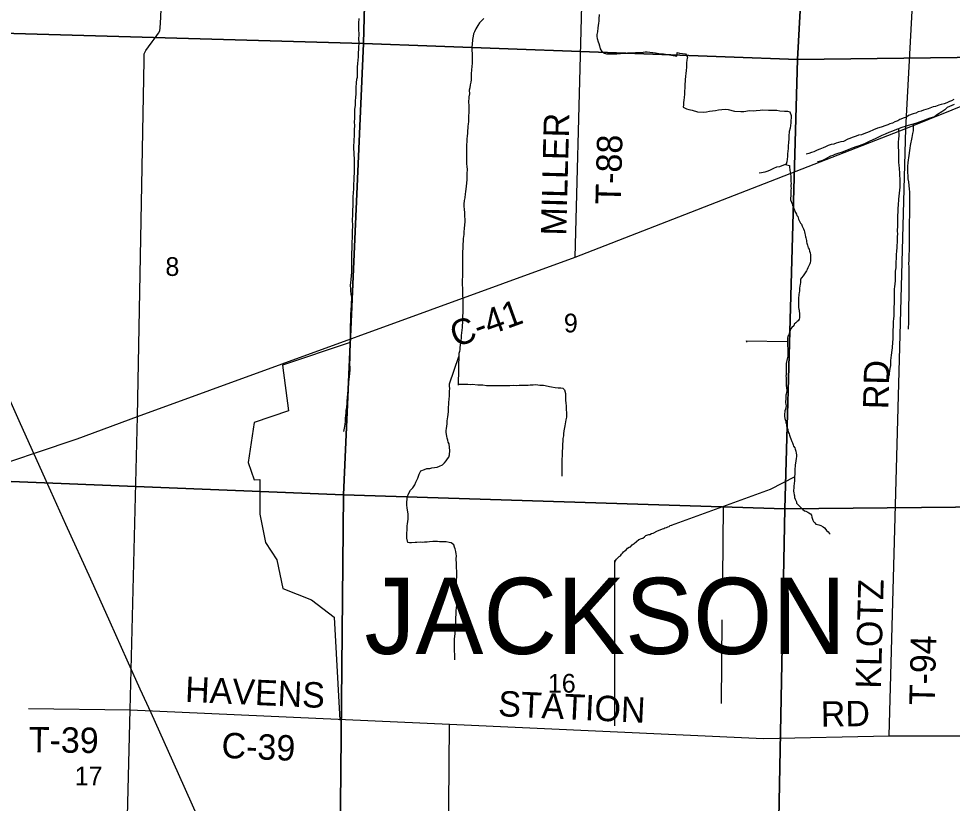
# Model space of a CAD drawing. Extents: x 1588073 to 2013523, y 1090242 to 1357120.
# Drawn here: x 1754621 to 1765643, y 1203633 to 1212899 of the extents above; entities that cross this region are included whole.
import ezdxf

# ---------------------------------------------------------------- set-up
doc = ezdxf.new("R2010")
doc.units = 0
for name, color, linetype in [('GM_X_County_Road', 7, 'Continuous'), ('GM_X_County_Road_Text', 7, 'Continuous'), ('GM_X_Minor_River', 7, 'Continuous'), ('GM_X_Rail_Line', 7, 'Continuous'), ('GM_X_Section', 7, 'Continuous'), ('GM_X_Section_Text', 7, 'Continuous'), ('GM_X_State_Route', 7, 'Continuous'), ('GM_X_Township_Road', 7, 'Continuous'), ('GM_X_Township_Road_Text', 7, 'Continuous'), ('GM_X_Township_Text', 7, 'Continuous')]:
    doc.layers.add(name, color=color, linetype=linetype)

msp = doc.modelspace()

# ---------------------------------------------------------------- linework, layer by layer
at = {"layer": 'GM_X_County_Road'}
for points in [[(1756023, 1208199), (1761191, 1210081), (1765096, 1211602), (1766978, 1212363), (1767188, 1212436), (1769131, 1212444)], [(1754830, 1207775), (1754830, 1207775), (1755311, 1207936), (1756023, 1208199)], [(1748340, 1207517), (1748351, 1207513), (1748389, 1207502), (1751177, 1207475), (1753182, 1207451), (1753244, 1207452), (1753738, 1207449), (1753898, 1207463), (1754315, 1207603), (1754830, 1207775)], [(1755938, 1204735), (1759706, 1204567), (1763414, 1204400), (1764898, 1204431), (1766414, 1204430)]]:
    msp.add_lwpolyline(points, dxfattribs=at)
at = {"layer": 'GM_X_Minor_River'}
for p, q in [((1758533, 1209074), (1757737, 1208807)), ((1763213, 1209094), (1763697, 1209086)), ((1763218, 1209079), (1763213, 1209094)), ((1757737, 1208807), (1757737, 1208807)), ((1757737, 1208807), (1757805, 1208266)), ((1757805, 1208266), (1757399, 1208130)), ((1757805, 1208266), (1757805, 1208266)), ((1757399, 1208130), (1757332, 1207657)), ((1757399, 1208130), (1757399, 1208130)), ((1757332, 1207657), (1757332, 1207657)), ((1757332, 1207657), (1757399, 1207454)), ((1757399, 1207454), (1757467, 1207455)), ((1757467, 1207455), (1757467, 1207049)), ((1763498, 1207344), (1763787, 1207493)), ((1762327, 1206918), (1763498, 1207344)), ((1763498, 1207344), (1763498, 1207344)), ((1762932, 1206284), (1762942, 1207142)), ((1757467, 1207049), (1757467, 1207049)), ((1757467, 1207049), (1757535, 1206711)), ((1757535, 1206711), (1757535, 1206711)), ((1757535, 1206711), (1757670, 1206508)), ((1757670, 1206508), (1757670, 1206508)), ((1757670, 1206508), (1757738, 1206170)), ((1761660, 1204549), (1761659, 1206499)), ((1757738, 1206170), (1757738, 1206170)), ((1757738, 1206170), (1758076, 1206035)), ((1758076, 1206035), (1758076, 1206035)), ((1758076, 1206035), (1758346, 1205832)), ((1758346, 1205832), (1758346, 1205832)), ((1758346, 1205832), (1758414, 1204616)), ((1762919, 1204812), (1762926, 1205801))]:
    msp.add_line(p, q, dxfattribs=at)
for points in [[(1758637, 1212901), (1758633, 1212844), (1758632, 1212782), (1758636, 1212706), (1758634, 1212664), (1758636, 1212612), (1758634, 1212558), (1758630, 1212474), (1758628, 1212447), (1758621, 1212369), (1758617, 1212327), (1758617, 1212259), (1758615, 1212203), (1758609, 1212179), (1758605, 1212147), (1758603, 1212084), (1758601, 1212060), (1758600, 1212018), (1758596, 1211962), (1758594, 1211936), (1758592, 1211900), (1758592, 1211878), (1758586, 1211826), (1758584, 1211778), (1758584, 1211713), (1758582, 1211689), (1758585, 1211625), (1758583, 1211599), (1758583, 1211535), (1758581, 1211513), (1758579, 1211473), (1758577, 1211449), (1758575, 1211393), (1758575, 1211359), (1758577, 1211323), (1758580, 1211218), (1758580, 1211178), (1758582, 1211104), (1758582, 1211076), (1758578, 1211032), (1758578, 1211006), (1758574, 1210928), (1758573, 1210895), (1758571, 1210837), (1758567, 1210799), (1758567, 1210773), (1758565, 1210749), (1758565, 1210683), (1758563, 1210643), (1758561, 1210595), (1758561, 1210561), (1758559, 1210539), (1758560, 1210438), (1758558, 1210404), (1758558, 1210338), (1758556, 1210310), (1758554, 1210264), (1758554, 1210242), (1758552, 1210170), (1758550, 1210148), (1758551, 1210101), (1758549, 1210035), (1758549, 1209903), (1758547, 1209871), (1758541, 1209809)], [(1760113, 1212901), (1760062, 1212848), (1760040, 1212820), (1760016, 1212780), (1760004, 1212744)], [(1761475, 1212949), (1761470, 1212896), (1761468, 1212868), (1761466, 1212846), (1761458, 1212792), (1761454, 1212744), (1761448, 1212712), (1761446, 1212690), (1761452, 1212664), (1761462, 1212626), (1761470, 1212604), (1761476, 1212580), (1761486, 1212544), (1761505, 1212512), (1761535, 1212490), (1761559, 1212484), (1761589, 1212482), (1761655, 1212482), (1761681, 1212484), (1761705, 1212486), (1761727, 1212486), (1761755, 1212490), (1761783, 1212492), (1761807, 1212494), (1761845, 1212494), (1761869, 1212497), (1761903, 1212499), (1761943, 1212501), (1761967, 1212501), (1761993, 1212505), (1762015, 1212507), (1762039, 1212507), (1762071, 1212503), (1762106, 1212501), (1762138, 1212497), (1762180, 1212489), (1762208, 1212485), (1762234, 1212482), (1762256, 1212478), (1762284, 1212474), (1762306, 1212470), (1762390, 1212457)], [(1760004, 1212744), (1759992, 1212720), (1759986, 1212694), (1759978, 1212654), (1759974, 1212592), (1759972, 1212565), (1759972, 1212519), (1759974, 1212491), (1759975, 1212435), (1759973, 1212405), (1759973, 1212365), (1759971, 1212343), (1759965, 1212287), (1759963, 1212257), (1759963, 1212178), (1759959, 1212150), (1759951, 1212116), (1759945, 1212082), (1759941, 1212054), (1759942, 1212010), (1759936, 1211976), (1759932, 1211904), (1759934, 1211882), (1759934, 1211785), (1759932, 1211757), (1759930, 1211721), (1759930, 1211685), (1759929, 1211655), (1759925, 1211629), (1759923, 1211605), (1759921, 1211579), (1759919, 1211547), (1759915, 1211511), (1759913, 1211481), (1759913, 1211447), (1759909, 1211408), (1759909, 1211380), (1759907, 1211356), (1759907, 1211324), (1759906, 1211266), (1759906, 1211222), (1759908, 1211184), (1759910, 1211154), (1759914, 1211116), (1759912, 1211070), (1759912, 1211038), (1759910, 1210999), (1759906, 1210955), (1759904, 1210921), (1759897, 1210853), (1759891, 1210831), (1759887, 1210785), (1759881, 1210753), (1759875, 1210707), (1759875, 1210685), (1759879, 1210644), (1759883, 1210610), (1759885, 1210566), (1759887, 1210528), (1759888, 1210500), (1759884, 1210464), (1759882, 1210420), (1759878, 1210380), (1759876, 1210352), (1759870, 1210304), (1759868, 1210272), (1759866, 1210235), (1759864, 1210189), (1759862, 1210147), (1759861, 1210095), (1759861, 1210003), (1759861, 1209963), (1759859, 1209939), (1759859, 1209849), (1759857, 1209820), (1759857, 1209762), (1759860, 1209708), (1759860, 1209674), (1759862, 1209626), (1759864, 1209600), (1759866, 1209562), (1759866, 1209456), (1759864, 1209432), (1759862, 1209383), (1759862, 1209361), (1759861, 1209327), (1759859, 1209305), (1759857, 1209279), (1759855, 1209251), (1759853, 1209221), (1759849, 1209189), (1759845, 1209159), (1759843, 1209127), (1759841, 1209101), (1759837, 1209075), (1759833, 1209045), (1759829, 1209016), (1759827, 1208992), (1759823, 1208970), (1759819, 1208944), (1759818, 1208910)], [(1762389, 1212457), (1762394, 1212498), (1762424, 1212492), (1762456, 1212489), (1762492, 1212483), (1762515, 1212445), (1762509, 1212411), (1762505, 1212375), (1762504, 1212328), (1762500, 1212286), (1762495, 1212250), (1762493, 1212218), (1762489, 1212176), (1762484, 1212108), (1762484, 1212080), (1762481, 1212048), (1762481, 1212006), (1762477, 1211968), (1762474, 1211938), (1762470, 1211910), (1762468, 1211882), (1762467, 1211854), (1762503, 1211835), (1762533, 1211827), (1762571, 1211819), (1762635, 1211798), (1762701, 1211793), (1762742, 1211797), (1762776, 1211805), (1762848, 1211816), (1762884, 1211822), (1762922, 1211827), (1762960, 1211829), (1762996, 1211825), (1763072, 1211808), (1763145, 1211801), (1763183, 1211803), (1763249, 1211814), (1763297, 1211812), (1763329, 1211813), (1763373, 1211819), (1763407, 1211821), (1763474, 1211820), (1763510, 1211820), (1763540, 1211817), (1763572, 1211817), (1763606, 1211811), (1763662, 1211806), (1763696, 1211806), (1763726, 1211797), (1763740, 1211757), (1763737, 1211669), (1763728, 1211605), (1763718, 1211567), (1763711, 1211511), (1763711, 1211477), (1763708, 1211439), (1763706, 1211395), (1763704, 1211367), (1763701, 1211333), (1763699, 1211301), (1763697, 1211273), (1763694, 1211239), (1763688, 1211209), (1763682, 1211181), (1763629, 1211161), (1763601, 1211151), (1763567, 1211146), (1763531, 1211130), (1763493, 1211108), (1763464, 1211098), (1763430, 1211087), (1763390, 1211079), (1763362, 1211073)], [(1765660, 1211945), (1765632, 1211929), (1765608, 1211919), (1765579, 1211906), (1765545, 1211894), (1765511, 1211886), (1765483, 1211878), (1765445, 1211861), (1765418, 1211857), (1765358, 1211834), (1765304, 1211820), (1765276, 1211808), (1765239, 1211799), (1765211, 1211781), (1765179, 1211775), (1765127, 1211754), (1765103, 1211736), (1765076, 1211728), (1765024, 1211709), (1764998, 1211691), (1764964, 1211681), (1764937, 1211665), (1764905, 1211656), (1764881, 1211644), (1764857, 1211638), (1764803, 1211619), (1764760, 1211605), (1764712, 1211585), (1764662, 1211564), (1764630, 1211550), (1764599, 1211538), (1764569, 1211529), (1764537, 1211523), (1764509, 1211513), (1764483, 1211503), (1764459, 1211496), (1764434, 1211484), (1764408, 1211474), (1764360, 1211448), (1764326, 1211443), (1764271, 1211427), (1764245, 1211418), (1764211, 1211412), (1764177, 1211400), (1764145, 1211386), (1764117, 1211375), (1764080, 1211359), (1764048, 1211345), (1764008, 1211328), (1763980, 1211320), (1763948, 1211308), (1763919, 1211300)], [(1765665, 1211887), (1765637, 1211873), (1765609, 1211861), (1765583, 1211849), (1765554, 1211822), (1765520, 1211800), (1765468, 1211768), (1765433, 1211739), (1765377, 1211723), (1765347, 1211711), (1765262, 1211680), (1765210, 1211661), (1765150, 1211645), (1765110, 1211634), (1765085, 1211626), (1765047, 1211612), (1764963, 1211581), (1764938, 1211569), (1764894, 1211553), (1764852, 1211534), (1764812, 1211518), (1764739, 1211483), (1764661, 1211448), (1764608, 1211422), (1764576, 1211408), (1764544, 1211397), (1764502, 1211387), (1764473, 1211375), (1764449, 1211365), (1764415, 1211350), (1764383, 1211338), (1764353, 1211326), (1764329, 1211319), (1764304, 1211309), (1764256, 1211293), (1764232, 1211283), (1764206, 1211274), (1764168, 1211254), (1764143, 1211240), (1764111, 1211224), (1764085, 1211217), (1764051, 1211207)], [(1765007, 1211597), (1765012, 1211512), (1765008, 1211484), (1765005, 1211436), (1765003, 1211408), (1765005, 1211382), (1765006, 1211340), (1765008, 1211304), (1765007, 1211196), (1765011, 1211172), (1765014, 1211125), (1765018, 1211077), (1765019, 1211045), (1765023, 1211009), (1765022, 1210909), (1765018, 1210873), (1765015, 1210839), (1765007, 1210767), (1765002, 1210695), (1765000, 1210661), (1764999, 1210618), (1764997, 1210576), (1764996, 1210530), (1764996, 1210486), (1764994, 1210458), (1764993, 1210390), (1764995, 1210356), (1764992, 1210324), (1764992, 1210284), (1764990, 1210256), (1764989, 1210224), (1764987, 1210196), (1764984, 1210152), (1764982, 1210112), (1764982, 1210088), (1764980, 1210064), (1764977, 1210033), (1764977, 1210001), (1764975, 1209957), (1764970, 1209917), (1764969, 1209845), (1764967, 1209805), (1764963, 1209763), (1764960, 1209735), (1764958, 1209705), (1764958, 1209681), (1764955, 1209639), (1764957, 1209605), (1764956, 1209529), (1764954, 1209499), (1764953, 1209428), (1764951, 1209390), (1764948, 1209354), (1764946, 1209322), (1764946, 1209294), (1764944, 1209264), (1764941, 1209220), (1764939, 1209192), (1764940, 1209158), (1764940, 1209116), (1764936, 1209078), (1764931, 1209010), (1764929, 1208984), (1764922, 1208926), (1764915, 1208862), (1764913, 1208804), (1764907, 1208768), (1764900, 1208740), (1764898, 1208710), (1764898, 1208684)], [(1765180, 1211653), (1765181, 1211575), (1765173, 1211543), (1765164, 1211497), (1765145, 1211401), (1765141, 1211369), (1765124, 1211257), (1765122, 1211231), (1765117, 1211197), (1765115, 1211156), (1765114, 1211094), (1765118, 1211030), (1765119, 1211006), (1765125, 1210972), (1765131, 1210928), (1765134, 1210884), (1765136, 1210852), (1765137, 1210814), (1765137, 1210749), (1765138, 1210695), (1765138, 1210635), (1765137, 1210587), (1765137, 1210555), (1765135, 1210523), (1765133, 1210381), (1765135, 1210343), (1765133, 1210160), (1765130, 1210112), (1765130, 1210074), (1765128, 1210048), (1765127, 1210004), (1765129, 1209974), (1765129, 1209926), (1765130, 1209872), (1765130, 1209830), (1765131, 1209806), (1765131, 1209765), (1765129, 1209727), (1765128, 1209681), (1765130, 1209639), (1765129, 1209589), (1765127, 1209531), (1765124, 1209293), (1765122, 1209260), (1765120, 1209234)], [(1763675, 1211176), (1763722, 1211163), (1763722, 1211137), (1763724, 1211121), (1763723, 1211105), (1763727, 1211091), (1763731, 1211072), (1763733, 1211058), (1763736, 1211042), (1763736, 1210998), (1763737, 1210974), (1763739, 1210958), (1763738, 1210928), (1763738, 1210914), (1763740, 1210898), (1763738, 1210874), (1763737, 1210842), (1763735, 1210826), (1763734, 1210760), (1763751, 1210711), (1763755, 1210695), (1763766, 1210675), (1763772, 1210659), (1763780, 1210641), (1763785, 1210623), (1763793, 1210608), (1763803, 1210590), (1763809, 1210576), (1763818, 1210562), (1763822, 1210546), (1763828, 1210530), (1763834, 1210516), (1763843, 1210499), (1763851, 1210485), (1763861, 1210471), (1763870, 1210449), (1763886, 1210417), (1763894, 1210396), (1763899, 1210382), (1763903, 1210362), (1763905, 1210346), (1763910, 1210324), (1763914, 1210310), (1763916, 1210294), (1763920, 1210280), (1763921, 1210264), (1763927, 1210246), (1763933, 1210225), (1763938, 1210207), (1763942, 1210191), (1763952, 1210175), (1763958, 1210153), (1763963, 1210135), (1763967, 1210111), (1763970, 1210079), (1763970, 1210041), (1763963, 1210017), (1763961, 1210003), (1763944, 1209973), (1763938, 1209955), (1763928, 1209937), (1763920, 1209921), (1763905, 1209897), (1763881, 1209861), (1763862, 1209840), (1763852, 1209822), (1763850, 1209800), (1763849, 1209780), (1763847, 1209762), (1763844, 1209738), (1763840, 1209718), (1763840, 1209704), (1763838, 1209686), (1763833, 1209662), (1763831, 1209646), (1763831, 1209626), (1763828, 1209610), (1763827, 1209554), (1763829, 1209533), (1763828, 1209487), (1763830, 1209469), (1763834, 1209455), (1763835, 1209439), (1763837, 1209421), (1763837, 1209385), (1763838, 1209365), (1763834, 1209349), (1763824, 1209329), (1763810, 1209323), (1763795, 1209307), (1763775, 1209290), (1763771, 1209272), (1763748, 1209252), (1763738, 1209238), (1763730, 1209222), (1763723, 1209202), (1763715, 1209182), (1763713, 1209166), (1763701, 1209151), (1763696, 1209127), (1763698, 1209104)], [(1758541, 1209809), (1758537, 1209787), (1758535, 1209743), (1758538, 1209715), (1758538, 1209690), (1758544, 1209642), (1758548, 1209612), (1758548, 1209580), (1758546, 1209556), (1758546, 1209498), (1758544, 1209474), (1758544, 1209446), (1758540, 1209422), (1758538, 1209372), (1758537, 1209318), (1758535, 1209286), (1758535, 1209131), (1758533, 1209109), (1758533, 1209049), (1758531, 1209027), (1758532, 1208965), (1758530, 1208913), (1758530, 1208889), (1758528, 1208818), (1758530, 1208776), (1758530, 1208750), (1758526, 1208704), (1758522, 1208674), (1758514, 1208608), (1758511, 1208570), (1758507, 1208544), (1758507, 1208518), (1758501, 1208465), (1758497, 1208429), (1758495, 1208383), (1758493, 1208359), (1758491, 1208307), (1758485, 1208271), (1758483, 1208249), (1758479, 1208209), (1758477, 1208181), (1758474, 1208141), (1758470, 1208111), (1758462, 1208064), (1758454, 1208022)], [(1763698, 1209104), (1763697, 1209062), (1763699, 1209044), (1763700, 1208996), (1763701, 1208964), (1763701, 1208914), (1763696, 1208896), (1763694, 1208882), (1763690, 1208862), (1763685, 1208848), (1763683, 1208826), (1763681, 1208808), (1763680, 1208790), (1763682, 1208774), (1763681, 1208698), (1763679, 1208678), (1763680, 1208660), (1763680, 1208630), (1763681, 1208592), (1763683, 1208578), (1763681, 1208564), (1763684, 1208543), (1763688, 1208503), (1763685, 1208489), (1763681, 1208465), (1763679, 1208451), (1763676, 1208417), (1763675, 1208365), (1763679, 1208343), (1763681, 1208327), (1763676, 1208307), (1763672, 1208289), (1763664, 1208267), (1763663, 1208221), (1763661, 1208205), (1763666, 1208179), (1763670, 1208165), (1763676, 1208147), (1763679, 1208127), (1763685, 1208110), (1763687, 1208092), (1763694, 1208066), (1763702, 1208048), (1763705, 1208014), (1763717, 1207996), (1763721, 1207982), (1763730, 1207957), (1763736, 1207937), (1763748, 1207907), (1763755, 1207889), (1763763, 1207867), (1763769, 1207851), (1763782, 1207832), (1763788, 1207816), (1763796, 1207792), (1763801, 1207768), (1763803, 1207748), (1763803, 1207724), (1763800, 1207708), (1763794, 1207674), (1763791, 1207652), (1763787, 1207626), (1763787, 1207606), (1763784, 1207592), (1763783, 1207514), (1763779, 1207498), (1763781, 1207484), (1763780, 1207438), (1763775, 1207412), (1763773, 1207373), (1763772, 1207351), (1763768, 1207333), (1763768, 1207319), (1763771, 1207301), (1763775, 1207277), (1763779, 1207263), (1763781, 1207245), (1763786, 1207225), (1763794, 1207209), (1763802, 1207195), (1763805, 1207177), (1763819, 1207160), (1763839, 1207140), (1763853, 1207128), (1763866, 1207113), (1763880, 1207103), (1763896, 1207087), (1763912, 1207081), (1763936, 1207070), (1763950, 1207064), (1763967, 1207050), (1763979, 1207036), (1763985, 1207013), (1763992, 1206989), (1763998, 1206975), (1764006, 1206961), (1764018, 1206945), (1764033, 1206931), (1764051, 1206926), (1764069, 1206922), (1764091, 1206914)], [(1759697, 1208306), (1759699, 1208347), (1759699, 1208369), (1759703, 1208403), (1759705, 1208447), (1759708, 1208503), (1759710, 1208527), (1759708, 1208563), (1759708, 1208587), (1759818, 1208910)], [(1759818, 1208910), (1759816, 1208874), (1759814, 1208840), (1759812, 1208810), (1759812, 1208686), (1759810, 1208650), (1759810, 1208593), (1759810, 1208569)], [(1759810, 1208581), (1759901, 1208582), (1759925, 1208584), (1759953, 1208580), (1759975, 1208582), (1760041, 1208576), (1760067, 1208576), (1760099, 1208574), (1760145, 1208568), (1760199, 1208566), (1760231, 1208565), (1760253, 1208565), (1760289, 1208567), (1760419, 1208567), (1760461, 1208569), (1760493, 1208567), (1760528, 1208569), (1760572, 1208571), (1760636, 1208572), (1760658, 1208574), (1760694, 1208576), (1760728, 1208578), (1760774, 1208572), (1760816, 1208570), (1760838, 1208568), (1760886, 1208556), (1760912, 1208550), (1760956, 1208544), (1760988, 1208541), (1761020, 1208539), (1761044, 1208535), (1761066, 1208515), (1761077, 1208473), (1761077, 1208394), (1761079, 1208360), (1761083, 1208326), (1761085, 1208280), (1761087, 1208248), (1761089, 1208218), (1761087, 1208194), (1761081, 1208162), (1761075, 1208136), (1761068, 1208090), (1761058, 1208030), (1761052, 1207995), (1761052, 1207971), (1761046, 1207941), (1761044, 1207909), (1761042, 1207873), (1761042, 1207821), (1761038, 1207795), (1761036, 1207765), (1761036, 1207729), (1761035, 1207703), (1761035, 1207522), (1761033, 1207498)], [(1759769, 1205328), (1759769, 1205392), (1759767, 1205430), (1759764, 1205486), (1759764, 1205508), (1759766, 1205570), (1759772, 1205638), (1759778, 1205709), (1759782, 1205755), (1759782, 1205821), (1759785, 1205871), (1759787, 1205911), (1759791, 1205943), (1759793, 1205973), (1759793, 1206166), (1759791, 1206188), (1759790, 1206260), (1759792, 1206320), (1759792, 1206378), (1759790, 1206408), (1759790, 1206430), (1759788, 1206462), (1759786, 1206521), (1759790, 1206555), (1759784, 1206581), (1759780, 1206605), (1759773, 1206637), (1759765, 1206659), (1759757, 1206685), (1759725, 1206707), (1759703, 1206713), (1759667, 1206721), (1759611, 1206720), (1759587, 1206722), (1759565, 1206724), (1759511, 1206724), (1759469, 1206722), (1759443, 1206716), (1759413, 1206716), (1759387, 1206714), (1759359, 1206716), (1759323, 1206712), (1759301, 1206712), (1759260, 1206707), (1759236, 1206707), (1759214, 1206711), (1759204, 1206763), (1759204, 1206828), (1759206, 1206860), (1759208, 1206882), (1759208, 1206910), (1759210, 1206934), (1759214, 1206962), (1759218, 1206988), (1759220, 1207014), (1759218, 1207050), (1759209, 1207118), (1759205, 1207158), (1759205, 1207182), (1759209, 1207231), (1759211, 1207257), (1759223, 1207289), (1759245, 1207329), (1759273, 1207359), (1759297, 1207395), (1759311, 1207425), (1759323, 1207449), (1759333, 1207473), (1759341, 1207496), (1759347, 1207518), (1759368, 1207560), (1759410, 1207576), (1759440, 1207586), (1759473, 1207586), (1759497, 1207594), (1759531, 1207600), (1759561, 1207604), (1759589, 1207613), (1759623, 1207631), (1759647, 1207655), (1759669, 1207677), (1759685, 1207699), (1759699, 1207721), (1759708, 1207747), (1759710, 1207801), (1759708, 1207833), (1759704, 1207877), (1759692, 1207899), (1759688, 1207922), (1759678, 1207946), (1759674, 1207970), (1759668, 1208012), (1759668, 1208034), (1759670, 1208060), (1759676, 1208086), (1759679, 1208116), (1759681, 1208148), (1759685, 1208172), (1759687, 1208196), (1759695, 1208256), (1759697, 1208306)], [(1761657, 1206441), (1761658, 1206461), (1761662, 1206493), (1761679, 1206515), (1761693, 1206533), (1761710, 1206546), (1761724, 1206556), (1761736, 1206574), (1761751, 1206587), (1761763, 1206603), (1761782, 1206618), (1761798, 1206630), (1761810, 1206644), (1761829, 1206657), (1761843, 1206663), (1761863, 1206687), (1761886, 1206700), (1761941, 1206747), (1761975, 1206762), (1761990, 1206766), (1762008, 1206781), (1762026, 1206795), (1762059, 1206806), (1762073, 1206809), (1762093, 1206819), (1762111, 1206825), (1762162, 1206849), (1762192, 1206863), (1762223, 1206874), (1762237, 1206877), (1762251, 1206885), (1762269, 1206891), (1762283, 1206896), (1762299, 1206900), (1762312, 1206914), (1762332, 1206919)], [(1764091, 1206914), (1764117, 1206897), (1764133, 1206885), (1764148, 1206867), (1764156, 1206853), (1764178, 1206838), (1764188, 1206824), (1764201, 1206812)]]:
    msp.add_lwpolyline(points, dxfattribs=at)
at = {"layer": 'GM_X_Rail_Line'}
msp.add_lwpolyline([(1762274, 1191202), (1762241, 1191275), (1761533, 1192842), (1760970, 1194091), (1760415, 1195321), (1759947, 1196359), (1759540, 1197259), (1759211, 1197990), (1758923, 1198626), (1756824, 1203275), (1756439, 1204131), (1756183, 1204700), (1756056, 1204979), (1755969, 1205174), (1755700, 1205772), (1755471, 1206278), (1755179, 1206926), (1755002, 1207318), (1754804, 1207757), (1754643, 1208116), (1753615, 1210421)], dxfattribs=at)
at = {"layer": 'GM_X_Section'}
for points in [[(1753721, 1218175), (1758837, 1218150), (1758691, 1212606), (1753594, 1212752), (1753597, 1218177)], [(1759031, 1218148), (1764126, 1218139), (1763814, 1212417), (1758691, 1212606), (1758837, 1218150)], [(1764350, 1218132), (1769462, 1218143), (1769153, 1212483), (1763814, 1212417), (1764126, 1218139)], [(1753594, 1212752), (1758691, 1212606), (1758457, 1207275), (1753547, 1207474)], [(1758691, 1212606), (1763814, 1212417), (1763664, 1207109), (1758457, 1207275)], [(1769153, 1212483), (1768903, 1207162), (1763664, 1207109), (1763814, 1212417)], [(1753547, 1207474), (1758457, 1207275), (1758404, 1201985), (1753407, 1202156)], [(1758457, 1207275), (1763664, 1207109), (1763564, 1201823), (1758404, 1201985)], [(1768903, 1207162), (1768847, 1201856), (1763564, 1201823), (1763664, 1207109)]]:
    msp.add_lwpolyline(points, close=True, dxfattribs=at)
at = {"layer": 'GM_X_State_Route'}
for points in [[(1756023, 1208199), (1756102, 1212406), (1756103, 1212483), (1756121, 1212524), (1756152, 1212568), (1756198, 1212626), (1756233, 1212672), (1756270, 1212729), (1756288, 1212755), (1756292, 1212789), (1756300, 1212913), (1756387, 1215182), (1756380, 1215243), (1756358, 1215281), (1756232, 1215457), (1756185, 1215556), (1756167, 1215678), (1756196, 1218155)], [(1752841, 1186194), (1753004, 1191531), (1753114, 1194718), (1753174, 1196805), (1753232, 1198124), (1753415, 1198218), (1754735, 1198719), (1755798, 1199012), (1755870, 1202063), (1755938, 1204735), (1756023, 1208199)]]:
    msp.add_lwpolyline(points, dxfattribs=at)
at = {"layer": 'GM_X_Township_Road'}
for points in [[(1765096, 1211602), (1765443, 1218107)], [(1761191, 1210081), (1761325, 1215142), (1761325, 1215142)], [(1764898, 1204431), (1765096, 1211602)], [(1754738, 1204754), (1755938, 1204735)], [(1759662, 1199261), (1759706, 1204567)]]:
    msp.add_lwpolyline(points, dxfattribs=at)

# ---------------------------------------------------------------- texts
at = {"layer": 'GM_X_County_Road_Text'}
for s, rotation, p in [('C-41', 19.9544, (1759780, 1209014)), ('HAVENS', 357.4587, (1756581, 1204831)), ('STATION', 357.3406, (1760277, 1204663)), ('RD', 0.9882, (1764093, 1204536)), ('C-39', 357.5998, (1757011, 1204170))]:
    msp.add_text(s, height=300, rotation=rotation, dxfattribs=at).set_placement(p)
at = {"layer": 'GM_X_Section_Text'}
for s, p in [('8', (1756353, 1209861)), ('9', (1761057, 1209194)), ('16', (1760868, 1204940)), ('17', (1755282, 1203845))]:
    msp.add_text(s, height=221, rotation=0, dxfattribs=at).set_placement(p)
at = {"layer": 'GM_X_Township_Road_Text'}
for s, rotation, p in [('MILLER', 88.5218, (1761085, 1210334)), ('T-88', 88.585, (1761729, 1210701)), ('RD', 88.5194, (1764888, 1208284)), ('KLOTZ', 88.5312, (1764800, 1204984)), ('T-94', 88.5863, (1765434, 1204788)), ('T-39', 359.2931, (1754739, 1204236))]:
    msp.add_text(s, height=300, rotation=rotation, dxfattribs=at).set_placement(p)
at = {"layer": 'GM_X_Township_Text'}
msp.add_text('JACKSON', height=900, rotation=0, dxfattribs=at).set_placement((1758703, 1205396))

doc.saveas('drawing.dxf')
